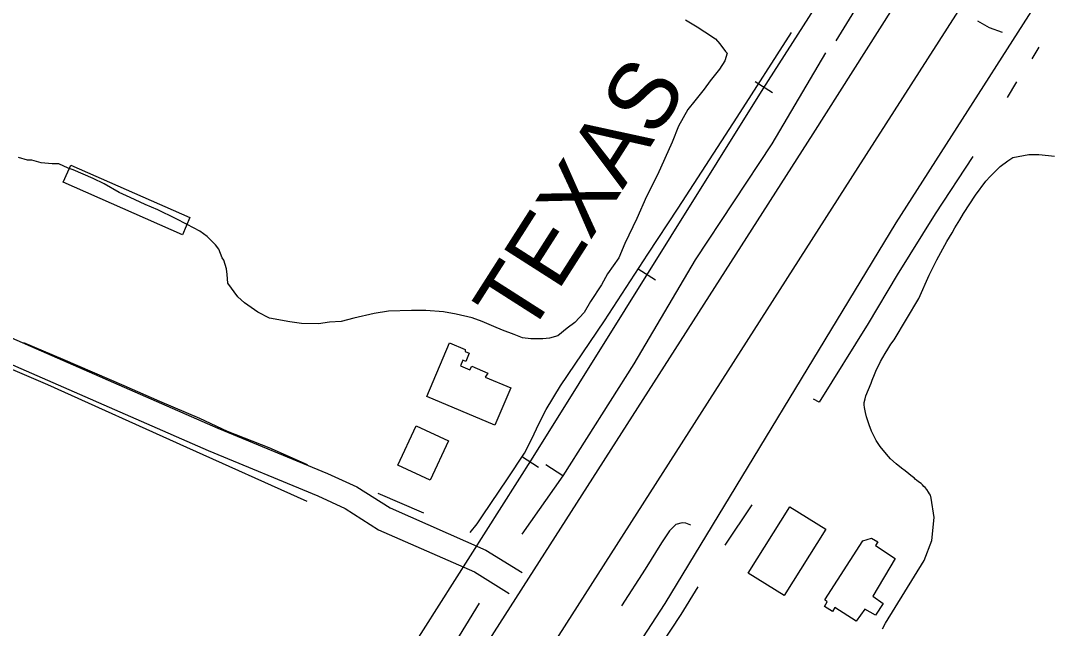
# Model space of a CAD drawing. Extents: x 3297716 to 3335574, y 688621 to 713991.
# Drawn here: x 3314468 to 3315727, y 696157 to 696901 of the extents above; entities that cross this region are included whole.
import ezdxf

# ---------------------------------------------------------------- set-up
doc = ezdxf.new("R2010")
doc.units = 0
for name, color, linetype in [('V-BLDG-OTLN', 7, 'Continuous'), ('V-RAIL-IDEN', 7, 'Continuous'), ('V-RAIL-TRAK', 7, 'Continuous'), ('V-ROAD-CNTR', 7, 'Continuous'), ('V-SITE-VEGE', 7, 'Continuous'), ('V-TOPO-SHOR', 7, 'Continuous')]:
    doc.layers.add(name, color=color, linetype=linetype)

msp = doc.modelspace()

# ---------------------------------------------------------------- linework, layer by layer
at = {"layer": 'V-BLDG-OTLN'}
for points in [[(3314528.9, 696723.9), (3314674.7, 696659.7), (3314665.5, 696638.8), (3314519.7, 696703)], [(3315047.9, 696405.7), (3314964.4, 696440.9), (3314992.1, 696506.7), (3315011.6, 696498.6), (3315011.4, 696496), (3315016.5, 696493.8), (3315012.3, 696483.8), (3315008.6, 696485.4), (3315005.6, 696478.4), (3315017.3, 696473.7), (3315019.7, 696478), (3315039.2, 696469.5), (3315036, 696464.7), (3315067.1, 696451.4)], [(3314951.5, 696405), (3314990.9, 696386.6), (3314968.7, 696338.8), (3314929.2, 696357.1)], [(3315401.7, 696197.4), (3315357.8, 696224.8), (3315408.7, 696306.1), (3315452.6, 696278.7)], [(3315513.2, 696173.3), (3315500.3, 696180.9), (3315489.9, 696166.1), (3315463.8, 696182.9), (3315460.9, 696177.8), (3315451.2, 696184.2), (3315454.4, 696189.7), (3315451.3, 696192.1), (3315498.1, 696264.4), (3315508.4, 696267.8), (3315516.2, 696263), (3315513.4, 696258.7), (3315537.6, 696242.7), (3315510, 696196.9), (3315522.9, 696187.7)]]:
    msp.add_lwpolyline(points, close=True, dxfattribs=at)
at = {"layer": 'V-RAIL-TRAK'}
for points in [[(3316611.7, 698753.5), (3316216.5, 698133.1), (3315831.8, 697530.3), (3315375.7, 696817.2), (3315094.4, 696366.7), (3314883.2, 696034.9), (3314608.6, 695612.7), (3314448.5, 695352.3), (3314153, 694886.2), (3313865.1, 694438.2), (3313614.2, 694040.9), (3313597.3, 694014.3)], [(3315387.3, 696812.3), (3315366.3, 696825.8)], [(3315244.4, 696583.4), (3315223.2, 696596.6)], [(3315101.3, 696354.3), (3315080.2, 696367.7)]]:
    msp.add_lwpolyline(points, dxfattribs=at)
at = {"layer": 'V-ROAD-CNTR'}
for points in [[(3316582.4, 698566.3), (3316230.2, 698008.5), (3315953, 697575.6), (3315436.8, 696762.2), (3315027.3, 696122.5), (3314649, 695523.1), (3314444.2, 695203), (3314172.9, 694779.1), (3313903.1, 694354.3), (3313688.4, 694014.4)], [(3316710.9, 698484.2), (3316345.8, 697916.9), (3316052.4, 697451.6), (3315775.1, 697023.9), (3315538.3, 696653.2), (3315255.8, 696187.9), (3314991, 695780.8), (3314661.9, 695266.3), (3314337, 694761.5), (3314014.8, 694257.6), (3313864.9, 694014.6)], [(3316589.1, 698460.1), (3316159.9, 697770.8), (3315870.8, 697312.4), (3315491.6, 696721), (3315062.5, 696049.6), (3314577.4, 695292.1), (3314229.7, 694736.4), (3313961.4, 694319.8), (3313768.8, 694014.5)], [(3313631.6, 696868.3), (3313726.6, 696824.9), (3314055, 696684.8), (3314247.8, 696604.9), (3314430, 696524.3), (3314708.9, 696402.4), (3314843.1, 696346.9), (3314879, 696330.3), (3314919.7, 696304.6), (3315036.8, 696253), (3315081.1, 696225.7)], [(3313619.9, 696840.7), (3313714.5, 696797.5), (3314043.3, 696657.1), (3314236, 696577.4), (3314418, 696496.8), (3314697.2, 696374.8), (3314831.1, 696319.4), (3314864.7, 696303.9), (3314905.6, 696278), (3315022.8, 696226.4), (3315065.3, 696200.2)]]:
    msp.add_lwpolyline(points, dxfattribs=at)
at = {"layer": 'V-SITE-VEGE'}
for p, q in [((3315280.9, 696901.6), (3315295.3, 696893.1)), ((3315295.3, 696893.1), (3315304.5, 696886.8)), ((3315304.5, 696886.8), (3315317.8, 696878.4)), ((3315317.8, 696878.4), (3315322.9, 696872.2)), ((3315322.9, 696872.2), (3315330, 696862.8)), ((3315332.1, 696860.7), (3315328.9, 696851.5)), ((3315330, 696862.8), (3315332.1, 696860.7)), ((3315328.9, 696851.5), (3315322.6, 696841.2)), ((3315322.6, 696841.2), (3315311.1, 696826.9)), ((3315311.1, 696826.9), (3315303.7, 696816.7)), ((3315303.7, 696816.7), (3315292.2, 696802.4)), ((3315292.2, 696802.4), (3315283.8, 696792.1)), ((3315283.8, 696792.1), (3315272.3, 696771.6)), ((3315272.3, 696771.6), (3315264.8, 696752.1)), ((3315264.8, 696752.1), (3315246.8, 696712.1)), ((3314476.2, 696730), (3314464.9, 696733.2)), ((3314481.3, 696729.9), (3314476.2, 696730)), ((3314492.6, 696726.7), (3314481.3, 696729.9)), ((3314506.1, 696725.5), (3314492.6, 696726.7)), ((3314514.3, 696725.4), (3314506.1, 696725.5)), ((3314525.6, 696720.1), (3314514.3, 696725.4)), ((3314531.8, 696718), (3314525.6, 696720.1)), ((3314556.4, 696707.4), (3314531.8, 696718)), ((3314569.8, 696701.1), (3314556.4, 696707.4)), ((3315246.8, 696712.1), (3315233.1, 696685.4)), ((3314588.2, 696690.5), (3314569.8, 696701.1)), ((3314601.6, 696684.2), (3314588.2, 696690.5)), ((3314620, 696675.7), (3314601.6, 696684.2)), ((3315233.1, 696685.4), (3315221.5, 696658.7)), ((3314635.4, 696669.4), (3314620, 696675.7)), ((3314657, 696658.8), (3314635.4, 696669.4)), ((3314671.4, 696651.4), (3314657, 696658.8)), ((3315221.5, 696658.7), (3315206.7, 696627.9)), ((3314686.8, 696643), (3314671.4, 696651.4)), ((3314696, 696636.7), (3314686.8, 696643)), ((3314706.2, 696626.3), (3314696, 696636.7)), ((3314710.2, 696621.1), (3314706.2, 696626.3)), ((3314714.2, 696610.7), (3314710.2, 696621.1)), ((3315206.7, 696627.9), (3315199.3, 696610.4)), ((3314716.3, 696607.6), (3314714.2, 696610.7)), ((3314719.3, 696597.2), (3314716.3, 696607.6)), ((3315199.3, 696610.4), (3315185.6, 696591)), ((3314720.2, 696590), (3314719.3, 696597.2)), ((3315185.6, 696591), (3315178.3, 696577.6)), ((3314721.1, 696579.7), (3314720.2, 696590)), ((3314733.3, 696563), (3314721.1, 696579.7)), ((3315178.3, 696577.6), (3315164.6, 696557.2)), ((3314741.5, 696555.7), (3314733.3, 696563)), ((3314757.9, 696544.2), (3314741.5, 696555.7)), ((3315164.6, 696557.2), (3315157.2, 696543.8)), ((3314772.2, 696536.8), (3314757.9, 696544.2)), ((3314900.3, 696542.6), (3314875.4, 696536.7)), ((3314917.8, 696545.5), (3314900.3, 696542.6)), ((3314945.7, 696546.2), (3314917.8, 696545.5)), ((3314963.3, 696546), (3314945.7, 696546.2)), ((3314984.9, 696544.7), (3314963.3, 696546)), ((3315000.4, 696541.5), (3314984.9, 696544.7)), ((3315019.9, 696537.1), (3315000.4, 696541.5)), ((3315157.2, 696543.8), (3315145.7, 696531.6)), ((3314797, 696532.4), (3314772.2, 696536.8)), ((3314811.4, 696530.2), (3314797, 696532.4)), ((3314832, 696529.9), (3314811.4, 696530.2)), ((3314845.5, 696531.8), (3314832, 696529.9)), ((3314859.9, 696532.7), (3314845.5, 696531.8)), ((3314875.4, 696536.7), (3314859.9, 696532.7)), ((3315032.2, 696532.8), (3315019.9, 696537.1)), ((3315046.6, 696526.5), (3315032.2, 696532.8)), ((3315145.7, 696531.6), (3315136.4, 696524.5)), ((3315056.9, 696522.2), (3315046.6, 696526.5)), ((3315071.3, 696516.9), (3315056.9, 696522.2)), ((3315081.6, 696512.7), (3315071.3, 696516.9)), ((3315124.9, 696515.3), (3315114.6, 696512.3)), ((3315136.4, 696524.5), (3315124.9, 696515.3)), ((3315091.9, 696511.5), (3315081.6, 696512.7)), ((3315106.3, 696511.4), (3315091.9, 696511.5)), ((3315114.6, 696512.3), (3315106.3, 696511.4))]:
    msp.add_line(p, q, dxfattribs=at)
for points in [[(3315558.5, 696342.8), (3315549.5, 696350), (3315545.1, 696353.2), (3315538.6, 696358.4), (3315531.9, 696364.7), (3315526.9, 696370.5), (3315519, 696380), (3315514.3, 696387.3), (3315508.4, 696398.6), (3315505.7, 696406.1), (3315502.5, 696416), (3315501, 696421.5), (3315499.8, 696427.6), (3315499.5, 696430.8), (3315499.4, 696433.7), (3315500.6, 696438), (3315501.7, 696441.8), (3315508, 696457.3), (3315509.4, 696461.1), (3315512.3, 696467.8), (3315514, 696472.1), (3315519.7, 696483.8), (3315525.2, 696493.7), (3315528.6, 696498.7), (3315532.1, 696504.8), (3315536.1, 696510.1), (3315566.5, 696560.9), (3315579.1, 696589.2), (3315584, 696599.1), (3315588.3, 696608.2), (3315600.6, 696630.6), (3315607, 696641.1), (3315610.4, 696647.3), (3315616.7, 696657.2), (3315621, 696664.8), (3315635.7, 696687.3), (3315648.4, 696704.2), (3315653.5, 696710.1), (3315662.8, 696719.2), (3315666, 696722.1), (3315675.2, 696729.1), (3315681.6, 696733.3), (3315701, 696736.9), (3315713.2, 696737), (3315725.2, 696735.9), (3315732.4, 696735.1)], [(3315521.8, 696156.8), (3315525.5, 696163.8), (3315573, 696240.4), (3315582.4, 696264.8), (3315585.1, 696293), (3315581.7, 696316.5), (3315580.5, 696320.3), (3315579.3, 696322), (3315578.1, 696324.1), (3315576.1, 696327), (3315574, 696329.6), (3315572.6, 696331), (3315570.8, 696333), (3315569.1, 696334.5), (3315567.3, 696335.6), (3315565.8, 696337.1), (3315564.1, 696338.2), (3315562, 696339.9), (3315560.6, 696341.4), (3315558.5, 696342.8)]]:
    msp.add_lwpolyline(points, dxfattribs=at)
at = {"layer": 'V-TOPO-SHOR'}
for p, q in [((3315512, 696953.1), (3315465, 696876)), ((3315705.2, 696854.1), (3315713.8, 696868.1)), ((3315675, 696806.5), (3315686.2, 696826)), ((3315130.8, 696343.8), (3315110.3, 696357.3)), ((3314960.8, 696298.2), (3314905.1, 696322.3)), ((3315362.2, 696308.3), (3315329, 696259.1))]:
    msp.add_line(p, q, dxfattribs=at)
for points in [[(3315668.9, 696886), (3315652.9, 696891.9), (3315638.7, 696899.9)], [(3315017.4, 696274.5), (3315026.1, 696285.3), (3315032.7, 696295.1), (3315063.3, 696340.4), (3315084.2, 696371.7), (3315092.5, 696388.3), (3315101.8, 696408.5), (3315110.6, 696425.2), (3315128, 696453.8), (3315181.7, 696533.4), (3315234.7, 696615), (3315271.9, 696671.3), (3315344.1, 696782.7), (3315410.5, 696886.1)], [(3315452.4, 696861.4), (3315386.7, 696749.8), (3315292.9, 696608), (3315217.8, 696481), (3315130.8, 696343.8), (3315080.8, 696272.7)], [(3315632.6, 696734.6), (3315586.5, 696664.5), (3315539.9, 696589.9), (3315504.3, 696530.4), (3315444.4, 696434), (3315437.5, 696437.7)], [(3314818.1, 696312.6), (3314670.9, 696378.6), (3314500.8, 696455.1), (3314337, 696525.4)], [(3314818.4, 696357.3), (3314771.5, 696378.3), (3314720.7, 696398.2), (3314687, 696414.2), (3314637.8, 696435), (3314594.3, 696454.2), (3314519.7, 696486.3), (3314471.7, 696506.7)], [(3315287.4, 696283.7), (3315281.4, 696286.2), (3315277, 696286.5), (3315269.1, 696284.2), (3315261.5, 696276.8), (3315251.5, 696262), (3315231.8, 696229.6), (3315202.5, 696185)], [(3315160.2, 695997.4), (3315200.5, 696060.6), (3315275.6, 696174.2), (3315296.5, 696208.2)], [(3315028.5, 696188.2), (3314978.3, 696106.1), (3314950, 696061.6), (3314876.9, 695942.8), (3314757.1, 695759.3)]]:
    msp.add_lwpolyline(points, dxfattribs=at)

# ---------------------------------------------------------------- texts
at = {"layer": 'V-RAIL-IDEN'}
msp.add_text('TEXAS', height=83, rotation=57.4501, dxfattribs=at).set_placement((3315088, 696511.3))

doc.saveas('drawing.dxf')
